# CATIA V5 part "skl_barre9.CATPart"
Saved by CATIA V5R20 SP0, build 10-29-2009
Part number: skl_barre9
Publications: "Barre_10", "Axe_Pivot_b9b7", "Axe_Pivot_b9b1"
Bounding box of the stored display mesh (mm): x 0 to 394.671, y 0 to 313.648, z 0 to 20
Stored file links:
  C:\Users\Matthieu\Desktop\IFMA\Cours 2A\Thinkmotion\skl_barre9.CATPart
  C:\Users\Matthieu\Desktop\IFMA\Cours 2A\Thinkmotion\skl_IAO_bis.CATProduct
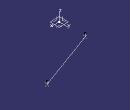
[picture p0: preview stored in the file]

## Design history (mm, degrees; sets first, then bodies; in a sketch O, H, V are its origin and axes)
AxisSystem1: origin (0, 0, 0), X (1, 0, 0), Y (0, 1, 0), Z (0, 0, 1)
Set1
  Point1 "Point.L": linked copy from another document
  Point2 "Point.H": linked copy from another document
  Plane1 "Plan_Ref": linked copy from another document
Body1 (main body)
  Line1 "Barre_10": type PtPt, FirstPoint Point1, SecondPoint Point2
  Line2 "Axe_Pivot_b9b7": type Normal, RefPoint Point1, RefSkin Plane1, Start 0, End 20
  Line3 "Axe_Pivot_b9b1": type Normal, RefPoint Point2, RefSkin Plane1, Start 0, End 20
